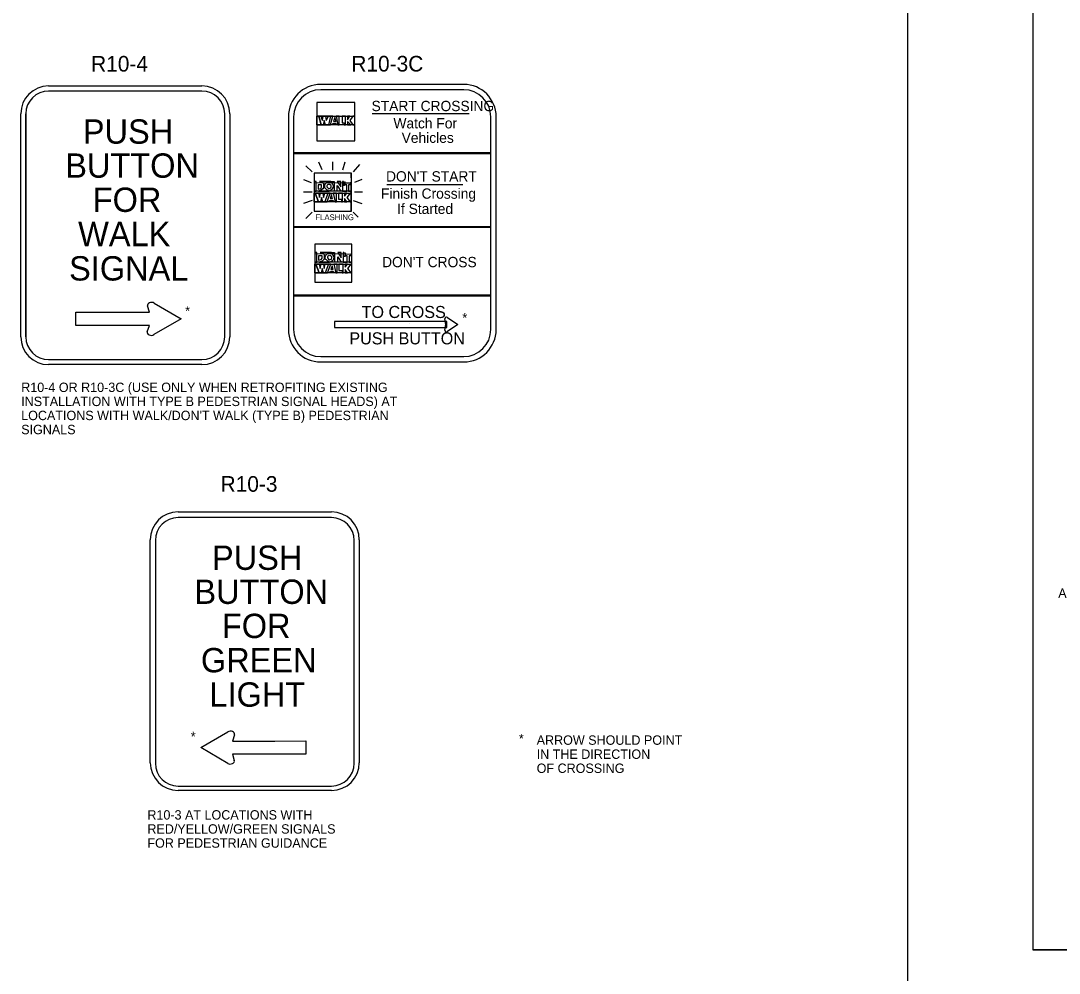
# Model space of a CAD drawing. Extents: x -344 to 940, y 22 to 1233.
# Drawn here: x -248 to 84.3, y 623.7 to 928.3 of the extents above; entities that cross this region are included whole.
import ezdxf

# ---------------------------------------------------------------- set-up
doc = ezdxf.new("R2010")
doc.units = 0
for name, color, linetype in [('1', 7, 'Continuous'), ('12', 7, 'Continuous'), ('2', 7, 'Continuous'), ('PLT-BNDY', 7, 'Continuous')]:
    doc.layers.add(name, color=color, linetype=linetype)

msp = doc.modelspace()

# ---------------------------------------------------------------- linework, layer by layer
at = {"layer": '1'}
for p, q in [((75.86, 1195.17), (75.86, 631.17)), ((-123.73, 831.32), (-123.73, 831.32)), ((861.86, 631.17), (75.86, 631.17)), ((75.86, 631.17), (661.86, 631.17))]:
    msp.add_line(p, q, dxfattribs=at)
at = {"layer": '12'}
for p, q in [((-112.27, 829.29), (-111.97, 831.2)), ((-111.97, 831.2), (-112.25, 833.01)), ((-108.17, 831.2), (-111.46, 828.88)), ((-111.45, 833.42), (-108.17, 831.2))]:
    msp.add_line(p, q, dxfattribs=at)
msp.add_lwpolyline([(-147.63, 830.18), (-111.65, 830.18), (-111.65, 832.08), (-147.63, 832.08)], close=True, dxfattribs=at)
for centre, start_param, end_param in [((-111.77, 833.09), 4.011799, 6.466875), ((-111.79, 829.2), 6.078068, 8.589712)]:
    msp.add_ellipse(centre, major_axis=(-0.492, 0), ratio=0.874034, start_param=start_param, end_param=end_param, dxfattribs=at)
at = {"layer": '2'}
for p, q in [((-239.09, 907.43), (-190.02, 907.43)), ((-106.24, 907.93), (-152, 907.93)), ((-190.04, 905.81), (-239.07, 905.81)), ((-106.24, 906.23), (-152, 906.23)), ((-247.99, 827.21), (-247.99, 898.53)), ((-246.37, 827.23), (-246.37, 898.51)), ((-246.37, 898.51), (-246.37, 827.23)), ((-246.37, 898.51), (-246.37, 827.23)), ((-182.74, 827.23), (-182.74, 898.51)), ((-181.12, 898.53), (-181.12, 827.21)), ((-162.37, 897.56), (-162.37, 829.55)), ((-160.67, 897.56), (-160.67, 829.55)), ((-153.24, 895.02), (-153.24, 897.77)), ((-153.24, 895.02), (-153.24, 897.77)), ((-153.24, 897.77), (-152.62, 897.77)), ((-152.62, 897.77), (-153.24, 897.77)), ((-153.24, 897.77), (-153.24, 895.02)), ((-151.87, 897.77), (-152.62, 897.77)), ((-152.62, 897.77), (-151.87, 895.02)), ((-151.87, 895.02), (-152.62, 897.77)), ((-151.49, 896.4), (-151.87, 897.77)), ((-151.87, 897.77), (-151.49, 896.4)), ((-151.87, 897.77), (-151.49, 896.4)), ((-151.24, 897.77), (-151.87, 897.77)), ((-151.49, 896.4), (-151.24, 897.77)), ((-150.49, 897.77), (-151.24, 897.77)), ((-150.49, 897.77), (-150.24, 896.4)), ((-149.49, 897.77), (-150.49, 897.77)), ((-150.24, 896.4), (-149.49, 897.77)), ((-148.87, 897.77), (-149.49, 897.77)), ((-148.87, 897.77), (-149.49, 895.02)), ((-148.87, 895.02), (-148.12, 897.77)), ((-148.12, 897.77), (-148.87, 897.77)), ((-135.53, 898.64), (-104.55, 898.64)), ((-97.57, 829.55), (-97.57, 897.56)), ((-95.87, 829.55), (-95.87, 897.56)), ((-151.87, 895.02), (-153.24, 895.02)), ((-153.24, 895.02), (-151.87, 895.02)), ((-151.87, 895.02), (-151.24, 895.02)), ((-150.87, 896.4), (-151.24, 895.02)), ((-151.24, 895.02), (-150.49, 895.02)), ((-150.49, 895.02), (-150.87, 896.4)), ((-150.49, 895.02), (-149.49, 895.02)), ((-149.49, 895.02), (-148.87, 895.02)), ((-97.57, 886.06), (-160.67, 886.06)), ((-97.57, 885.68), (-160.67, 885.68)), ((-156.74, 881.93), (-154.74, 879.93)), ((-151.58, 880.62), (-152.63, 883.06)), ((-148.14, 880.52), (-148.14, 883.22)), ((-144.28, 883.11), (-145.08, 880.55)), ((-139.62, 882.31), (-141.62, 879.93)), ((-157.49, 877.56), (-155.12, 876.56)), ((-138.87, 877.56), (-141.24, 876.56)), ((-130.88, 875.97), (-106.51, 875.97)), ((-157.49, 873.56), (-154.74, 873.56)), ((-154.74, 870.81), (-157.49, 869.81)), ((-154.12, 870.43), (-154.12, 873.18)), ((-154.12, 873.18), (-153.74, 873.18)), ((-153.74, 873.18), (-154.12, 873.18)), ((-154.12, 873.18), (-154.12, 870.43)), ((-152.74, 873.18), (-153.74, 873.18)), ((-153.74, 873.18), (-152.74, 870.43)), ((-152.74, 870.43), (-153.74, 873.18)), ((-152.74, 873.18), (-152.37, 871.81)), ((-152.12, 873.18), (-152.74, 873.18)), ((-152.37, 871.81), (-152.12, 873.18)), ((-151.37, 873.18), (-152.12, 873.18)), ((-151.74, 871.81), (-152.12, 870.43)), ((-151.37, 870.43), (-151.74, 871.81)), ((-151.37, 873.18), (-151.12, 871.81)), ((-150.74, 873.18), (-151.37, 873.18)), ((-151.12, 871.81), (-150.74, 873.18)), ((-149.74, 873.18), (-150.74, 873.18)), ((-149.74, 873.18), (-150.74, 870.43)), ((-149.99, 870.43), (-148.99, 873.18)), ((-148.99, 873.18), (-149.74, 873.18)), ((-141.62, 870.81), (-138.87, 869.81)), ((-141.24, 873.56), (-138.62, 873.56)), ((-152.74, 870.43), (-154.12, 870.43)), ((-154.12, 870.43), (-152.74, 870.43)), ((-152.74, 870.43), (-152.12, 870.43)), ((-152.12, 870.43), (-151.37, 870.43)), ((-151.37, 870.43), (-150.74, 870.43)), ((-150.74, 870.43), (-149.99, 870.43)), ((-154.74, 867.06), (-156.74, 865.06)), ((-141.62, 867.06), (-139.99, 865.43)), ((-97.57, 862.43), (-160.67, 862.43)), ((-97.57, 862.18), (-160.67, 862.18)), ((-98.62, 862.18), (-159.62, 862.18)), ((-153.92, 847.69), (-153.92, 850.44)), ((-153.92, 850.44), (-153.55, 850.44)), ((-153.55, 850.44), (-153.92, 850.44)), ((-153.92, 850.44), (-153.92, 847.69)), ((-152.55, 847.69), (-153.92, 847.69)), ((-153.92, 847.69), (-152.55, 847.69)), ((-152.55, 850.44), (-153.55, 850.44)), ((-153.55, 850.44), (-152.55, 847.69)), ((-152.55, 847.69), (-153.55, 850.44)), ((-152.55, 850.44), (-152.17, 849.07)), ((-151.92, 850.44), (-152.55, 850.44)), ((-152.55, 847.69), (-151.92, 847.69)), ((-152.17, 849.07), (-151.92, 850.44)), ((-151.17, 850.44), (-151.92, 850.44)), ((-151.55, 849.07), (-151.92, 847.69)), ((-151.92, 847.69), (-151.17, 847.69)), ((-151.17, 847.69), (-151.55, 849.07)), ((-151.17, 850.44), (-150.92, 849.07)), ((-150.55, 850.44), (-151.17, 850.44)), ((-151.17, 847.69), (-150.55, 847.69)), ((-150.92, 849.07), (-150.55, 850.44)), ((-149.55, 850.44), (-150.55, 850.44)), ((-149.55, 850.44), (-150.55, 847.69)), ((-150.55, 847.69), (-149.8, 847.69)), ((-149.8, 847.69), (-148.8, 850.44)), ((-148.8, 850.44), (-149.55, 850.44)), ((-205.34, 837.99), (-196.69, 832.96)), ((-97.57, 840.56), (-160.67, 840.56)), ((-97.57, 840.18), (-160.67, 840.18)), ((-230.34, 830.82), (-230.34, 835.1)), ((-230.34, 835.1), (-220.44, 835.08)), ((-220.44, 835.08), (-206.82, 835.08)), ((-206.82, 835.08), (-207.45, 837.08)), ((-220.44, 830.83), (-230.34, 830.82)), ((-206.82, 830.83), (-220.44, 830.83)), ((-207.51, 828.82), (-206.82, 830.83)), ((-196.69, 832.96), (-205.37, 827.92)), ((-152, 820.88), (-106.24, 820.88)), ((-190.02, 818.31), (-239.09, 818.31)), ((-239.07, 819.93), (-190.04, 819.93)), ((-152, 819.18), (-106.24, 819.18)), ((-197.64, 771.23), (-148.57, 771.23)), ((-148.59, 769.39), (-197.62, 769.39)), ((-206.54, 691.01), (-206.54, 762.33)), ((-204.92, 762.09), (-204.92, 690.82)), ((-141.29, 690.82), (-141.29, 762.09)), ((-139.67, 762.33), (-139.67, 691.01)), ((-190.42, 695.82), (-181.74, 700.86)), ((-179.6, 699.96), (-180.29, 697.94)), ((-180.29, 697.94), (-166.67, 697.94)), ((-166.67, 697.94), (-156.77, 697.95)), ((-156.77, 697.95), (-156.77, 693.68)), ((-181.77, 690.79), (-190.42, 695.82)), ((-166.67, 693.69), (-180.29, 693.69)), ((-180.29, 693.69), (-179.66, 691.7)), ((-156.77, 693.68), (-166.67, 693.69)), ((-148.57, 682.11), (-197.64, 682.11)), ((-197.62, 683.52), (-148.59, 683.52))]:
    msp.add_line(p, q, dxfattribs=at)
for points in [[(-153.24, 889.9), (-141.12, 889.9), (-141.12, 902.15), (-153.24, 902.15)], [(-153.24, 897.77), (-141.12, 897.77), (-141.12, 902.15), (-153.24, 902.15)], [(-147.87, 896.02), (-147.12, 896.02), (-147.49, 897.4)], [(-147.12, 897.77), (-146.49, 895.02), (-146.12, 895.02), (-146.12, 897.77)], [(-145.12, 897.77), (-145.12, 895.65), (-144.49, 895.65), (-144.49, 895.02), (-144.12, 895.02), (-144.12, 897.77)], [(-143.49, 897.77), (-143.49, 896.65), (-142.74, 897.77)], [(-141.74, 897.77), (-142.74, 896.4), (-141.74, 895.02), (-141.12, 895.02), (-141.12, 897.77)], [(-153.24, 889.9), (-141.12, 889.9), (-141.12, 895.02), (-153.24, 895.02)], [(-148.12, 895.02), (-148.12, 895.4), (-147.12, 895.4), (-146.87, 895.02)], [(-143.49, 896.02), (-143.49, 895.02), (-142.37, 895.02)], [(-154.12, 867.43), (-142.21, 867.43), (-142.21, 879.56), (-154.12, 879.56)], [(-154.07, 876.5), (-149.35, 876.61), (-144.73, 876.49), (-144.77, 876.76), (-144.61, 876.76), (-144.62, 876.75), (-144.62, 876.76), (-144.55, 876.76), (-144.36, 876.75), (-144.27, 876.43), (-142.21, 876.43), (-142.26, 879.54), (-154.12, 879.56)], [(-154.12, 873.81), (-153.49, 873.81), (-153.49, 876.93), (-154.12, 876.93)], [(-152.87, 875.81), (-152.87, 874.43), (-152.01, 874.66), (-151.71, 875.1), (-151.74, 875.56), (-151.79, 875.84), (-152.2, 875.84)], [(-152.37, 876.93), (-151.74, 876.93), (-151.37, 876.56), (-151.12, 876.18), (-151.12, 875.56), (-151.12, 874.81), (-151.37, 874.56), (-151.74, 874.18), (-152.74, 873.81), (-149.37, 873.81), (-149.95, 874.16), (-150.37, 874.56), (-150.74, 874.81), (-150.74, 875.56), (-150.6, 876.04), (-150.22, 876.41), (-149.74, 876.93), (-149.37, 876.93), (-152.37, 876.93)], [(-149.33, 875.9), (-149.6, 875.93), (-149.73, 875.88), (-149.92, 875.76), (-150.06, 875.49), (-150.04, 875.2), (-149.74, 874.81), (-149.37, 874.56), (-148.97, 874.74), (-148.74, 874.81), (-148.69, 875.18), (-148.64, 875.57), (-149.07, 875.92), (-149.06, 875.88), (-148.99, 875.91)], [(-149.37, 873.81), (-148.74, 874.18), (-148.37, 874.41), (-147.99, 874.81), (-147.95, 875.49), (-148.21, 876.09), (-148.59, 876.46), (-148.74, 876.93), (-149.37, 876.93), (-147.74, 876.93), (-147.74, 873.81)], [(-146.74, 876.93), (-145.62, 875.18), (-145.62, 876.93)], [(-146.74, 873.81), (-146.74, 875.56), (-145.62, 873.81)], [(-144.99, 876.93), (-144.99, 873.81), (-143.7, 873.81), (-143.7, 875.84), (-144.24, 875.84), (-144.24, 876.41), (-144.34, 876.78), (-144.36, 876.55), (-144.36, 875.58), (-144.76, 875.58), (-144.76, 875.62), (-144.76, 876.93)], [(-142.55, 876.43), (-142.55, 875.84), (-143.13, 875.84), (-143.13, 873.81), (-142.24, 873.81), (-142.24, 876.43)], [(-154.12, 873.18), (-142.24, 873.18), (-142.24, 873.81), (-154.12, 873.81)], [(-149.37, 870.43), (-149.06, 870.82), (-148.07, 870.82), (-147.99, 870.43)], [(-148.99, 871.43), (-148.24, 871.44), (-148.54, 872.69)], [(-147.99, 873.18), (-147.37, 870.43), (-146.99, 870.43), (-146.99, 873.18)], [(-146.37, 873.18), (-146.37, 871.18), (-145.37, 871.18), (-145.37, 870.43), (-144.99, 870.43), (-144.99, 873.18)], [(-144.37, 873.18), (-144.37, 872.18), (-143.62, 873.18)], [(-144.37, 871.43), (-144.37, 870.43), (-143.62, 870.43)], [(-142.62, 873.18), (-143.62, 871.81), (-142.62, 870.43), (-142.24, 870.43), (-142.24, 873.18)], [(-154.12, 867.43), (-142.24, 867.43), (-142.24, 870.43), (-154.12, 870.43)], [(-153.92, 844.69), (-142.02, 844.69), (-142.02, 856.83), (-153.92, 856.83)], [(-153.88, 853.76), (-149.16, 853.88), (-144.54, 853.75), (-144.58, 854.02), (-144.42, 854.02), (-144.43, 854.01), (-144.43, 854.02), (-144.36, 854.02), (-144.17, 854.02), (-144.08, 853.7), (-142.02, 853.69), (-142.06, 856.8), (-153.92, 856.82)], [(-153.92, 851.07), (-153.3, 851.07), (-153.3, 854.19), (-153.92, 854.19)], [(-152.17, 854.19), (-151.55, 854.19), (-151.17, 853.82), (-150.92, 853.44), (-150.92, 852.82), (-150.92, 852.07), (-151.17, 851.82), (-151.55, 851.44), (-152.55, 851.07), (-149.17, 851.07), (-149.76, 851.42), (-150.17, 851.82), (-150.55, 852.07), (-150.55, 852.82), (-150.41, 853.3), (-150.03, 853.68), (-149.55, 854.19), (-149.17, 854.19), (-152.17, 854.19)], [(-149.17, 851.07), (-148.55, 851.44), (-148.18, 851.67), (-147.8, 852.07), (-147.76, 852.75), (-148.02, 853.35), (-148.4, 853.73), (-148.55, 854.19), (-149.17, 854.19), (-147.55, 854.19), (-147.55, 851.07)], [(-146.55, 854.19), (-145.42, 852.44), (-145.42, 854.19)], [(-144.8, 854.19), (-144.8, 851.07), (-143.51, 851.07), (-143.51, 853.1), (-144.05, 853.1), (-144.05, 853.67), (-144.15, 854.04), (-144.17, 853.82), (-144.17, 852.85), (-144.57, 852.85), (-144.57, 852.88), (-144.57, 854.19)], [(-153.92, 850.44), (-142.05, 850.44), (-142.05, 851.07), (-153.92, 851.07)], [(-152.68, 853.07), (-152.68, 851.69), (-151.82, 851.93), (-151.52, 852.37), (-151.55, 852.82), (-151.6, 853.1), (-152.01, 853.1)], [(-149.14, 853.16), (-149.41, 853.19), (-149.54, 853.14), (-149.73, 853.02), (-149.87, 852.75), (-149.85, 852.46), (-149.55, 852.07), (-149.17, 851.82), (-148.78, 852), (-148.55, 852.07), (-148.5, 852.44), (-148.45, 852.83), (-148.88, 853.18), (-148.87, 853.14), (-148.8, 853.17)], [(-146.55, 851.07), (-146.55, 852.82), (-145.42, 851.07)], [(-142.36, 853.69), (-142.36, 853.1), (-142.94, 853.1), (-142.94, 851.07), (-142.05, 851.07), (-142.05, 853.69)], [(-153.92, 844.69), (-142.05, 844.69), (-142.05, 847.69), (-153.92, 847.69)], [(-149.17, 847.69), (-148.87, 848.08), (-147.88, 848.08), (-147.8, 847.69)], [(-148.8, 848.69), (-148.05, 848.7), (-148.35, 849.96)], [(-147.8, 850.44), (-147.17, 847.69), (-146.8, 847.69), (-146.8, 850.44)], [(-146.17, 850.44), (-146.17, 848.44), (-145.17, 848.44), (-145.17, 847.69), (-144.8, 847.69), (-144.8, 850.44)], [(-144.17, 850.44), (-144.17, 849.44), (-143.42, 850.44)], [(-144.17, 848.69), (-144.17, 847.69), (-143.42, 847.69)], [(-142.42, 850.44), (-143.42, 849.07), (-142.42, 847.69), (-142.05, 847.69), (-142.05, 850.44)]]:
    msp.add_lwpolyline(points, close=True, dxfattribs=at)
for centre, radius, start, end in [((-239.09, 898.53), 8.9, 90, 180), ((-190.02, 898.53), 8.9, 0, 90), ((-152, 897.56), 10.37, 90, 180), ((-106.24, 897.56), 10.37, 0, 90), ((-239.07, 898.51), 7.3, 90, 180), ((-190.04, 898.51), 7.3, 0, 90), ((-152, 897.56), 8.67, 90, 180), ((-106.24, 897.56), 8.67, 0, 90), ((-152, 829.55), 10.37, 180, 270), ((-152, 829.55), 8.67, 180, 270), ((-106.24, 829.55), 10.37, 270, 0), ((-106.24, 829.55), 8.67, 270, 0), ((-239.09, 827.21), 8.9, 180, 270), ((-239.07, 827.23), 7.3, 180, 270), ((-190.04, 827.23), 7.3, 270, 0), ((-190.02, 827.21), 8.9, 270, 0), ((-197.64, 762.33), 8.9, 90, 180), ((-148.57, 762.33), 8.9, 0, 90), ((-197.62, 762.09), 7.3, 90, 180), ((-148.59, 762.09), 7.3, 0, 90), ((-197.64, 691.01), 8.9, 180, 270), ((-197.62, 690.82), 7.3, 180, 270), ((-148.59, 690.82), 7.3, 270, 0), ((-148.57, 691.01), 8.9, 270, 0)]:
    msp.add_arc(centre, radius, start, end, dxfattribs=at)
for centre, major_axis, start_param, end_param in [((-206.17, 837.26), (-1.3, 0), 4.011799, 6.466875), ((-206.24, 828.62), (-1.3, 0), 6.078068, 8.589712), ((-180.87, 700.16), (1.3, 0), 6.078068, 8.589712), ((-180.94, 691.52), (1.3, 0), 4.011799, 6.466875)]:
    msp.add_ellipse(centre, major_axis=major_axis, ratio=0.7337, start_param=start_param, end_param=end_param, dxfattribs=at)
at = {"layer": 'PLT-BNDY'}
msp.add_lwpolyline([(35.86, 1210.17), (876.86, 1210.17), (876.86, 616.17), (35.86, 616.17)], close=True, dxfattribs=at)

# ---------------------------------------------------------------- texts
at = {"layer": '12'}
for s, height, p in [('TO CROSS', 3.857, (-138.93, 833.22)), ('PUSH BUTTON', 3.8575, (-142.85, 824.79))]:
    msp.add_text(s, height=height, dxfattribs=at).set_placement(p)
at = {"layer": '2'}
for s, height, p in [('R10-3C', 5, (-142.22, 912.06)), ('R10-4', 5, (-225.49, 912.03)), ('START CROSSING', 3.3, (-135.74, 899.38)), ('Watch For', 3.3, (-128.74, 893.86)), ('PUSH', 7.784, (-228.13, 888.97)), ('Vehicles', 3.3, (-126.12, 889.23)), ('BUTTON', 7.784, (-233.76, 878.09)), ("DON'T START", 3.3, (-131.11, 876.87)), ('FOR', 7.784, (-224.97, 867.16)), ('Finish Crossing', 3.3, (-132.73, 871.37)), ('If Started', 3.3, (-127.56, 866.5)), ('WALK', 7.784, (-229.64, 856.2)), ('FLASHING', 1.841, (-153.7, 864.52)), ('SIGNAL', 7.784, (-232.53, 845.21)), ("DON'T CROSS", 3.3, (-132.37, 849.47)), ('*', 3, (-195.39, 833.99)), ('*', 3, (-106.7, 831.79)), ('R10-4 OR R10-3C (USE ONLY WHEN RETROFITING EXISTING', 3, (-247.85, 809.56)), ('INSTALLATION WITH TYPE B PEDESTRIAN SIGNAL HEADS) AT', 3, (-247.85, 805.06)), ("LOCATIONS WITH WALK/DON'T WALK (TYPE B) PEDESTRIAN", 3, (-247.85, 800.56)), ('SIGNALS', 3, (-247.85, 796.06)), ('R10-3', 5, (-184.06, 777.66)), ('PUSH', 7.784, (-186.81, 752.67)), ('BUTTON', 7.784, (-192.43, 741.79)), ('AT LOCATIONS WITH WALKING', 3, (83.98, 743.72)), ('FOR', 7.784, (-183.64, 730.86)), ('GREEN', 7.784, (-190.35, 719.9)), ('LIGHT', 7.784, (-187.63, 708.91)), ('*', 3, (-193.59, 697.88)), ('*', 3, (-88.6, 697.22)), ('ARROW SHOULD POINT', 3, (-82.91, 696.73)), ('IN THE DIRECTION', 3, (-82.91, 692.23)), ('OF CROSSING', 3, (-82.91, 687.73)), ('R10-3 AT LOCATIONS WITH', 3, (-207.47, 672.81)), ('RED/YELLOW/GREEN SIGNALS', 3, (-207.47, 668.31)), ('FOR PEDESTRIAN GUIDANCE', 3, (-207.47, 663.81))]:
    msp.add_text(s, height=height, dxfattribs=at).set_placement(p)

doc.saveas('drawing.dxf')
